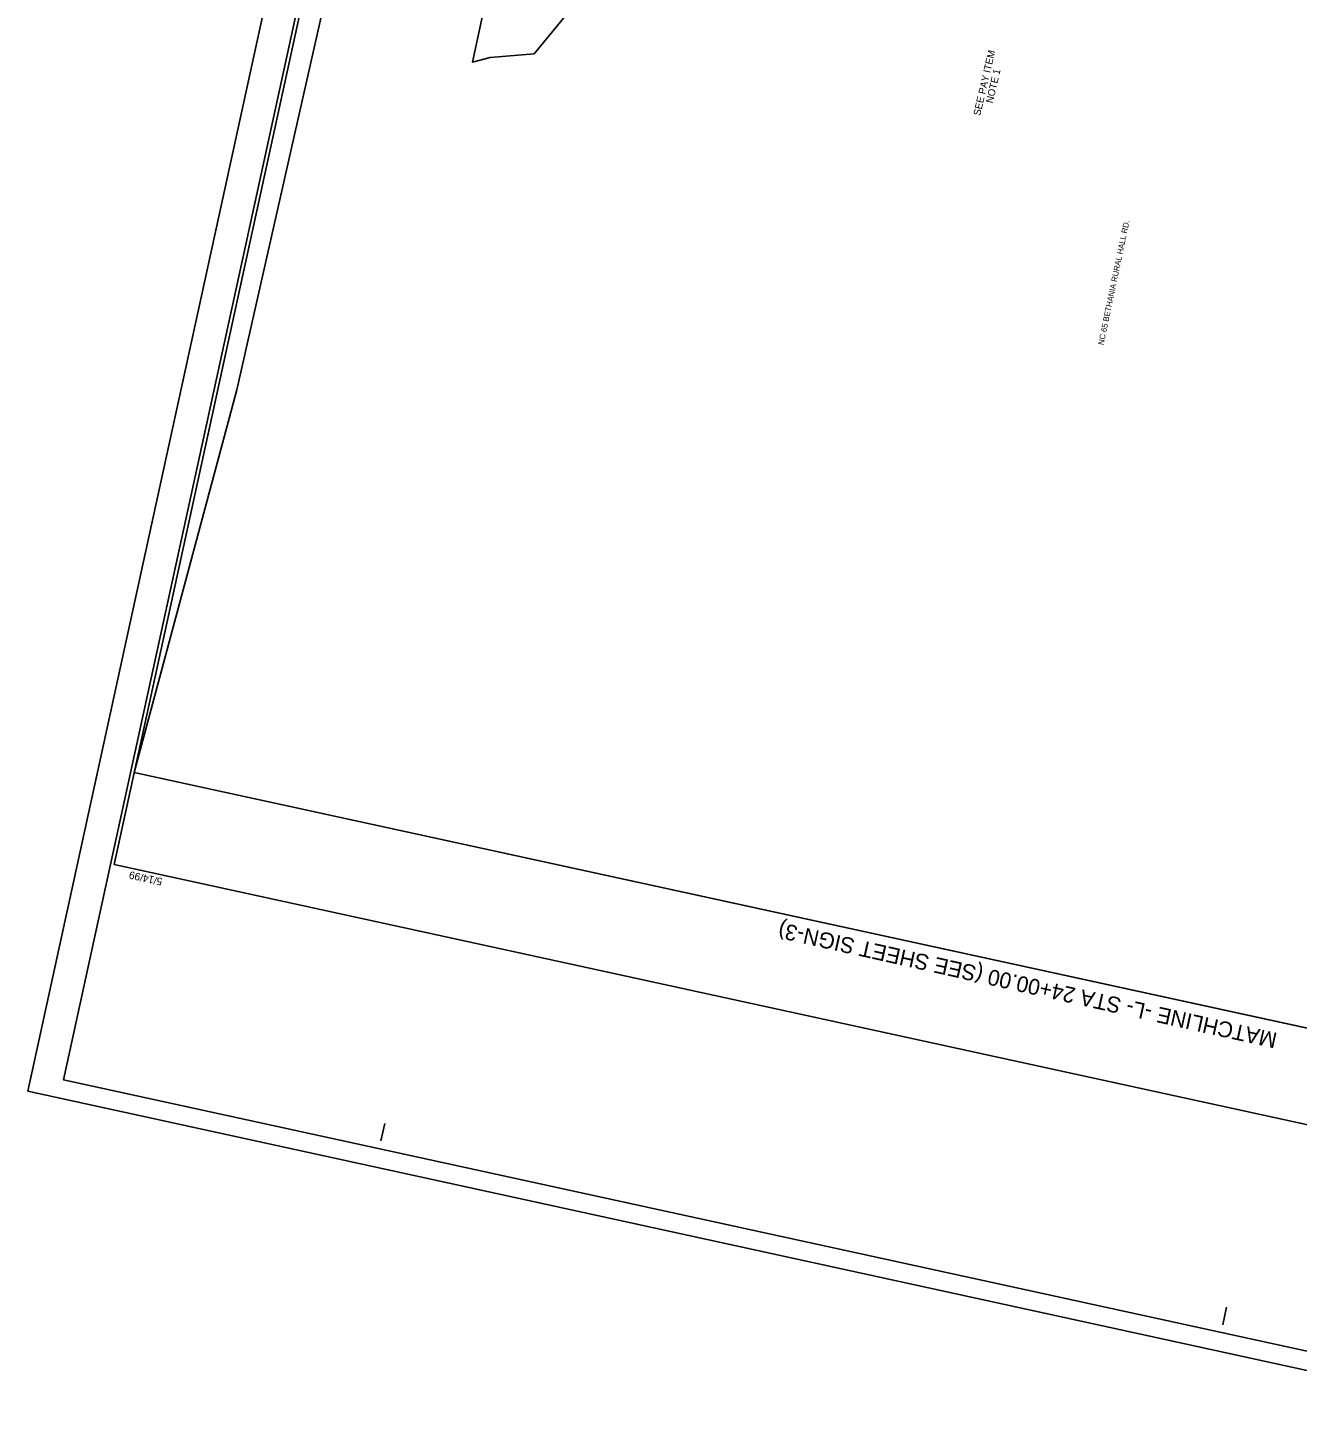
# Model space of a CAD drawing. Extents: x 1615829 to 1617263, y 900664 to 902544.
# Drawn here: x 1615829 to 1616713, y 900664 to 901639 of the extents above; entities that cross this region are included whole.
import ezdxf

# ---------------------------------------------------------------- set-up
doc = ezdxf.new("R2010")
doc.units = 0
for name, color, linetype in [('CTL Primary Horizontal and Vertical CELL', 7, 'Continuous'), ('CTL Primary Horizontal and Vertical Cogo Number', 7, 'Continuous'), ('CTL Secondary Horizontal and Vertical CELL', 7, 'Continuous'), ('Default', 7, 'Continuous'), ('Exist DTM Crownline Cogo Number', 7, 'Continuous'), ('Exist Roads Curbs Cogo Number', 7, 'Continuous'), ('Exist Roads Curbs Cogo Point CELL', 7, 'Continuous'), ('Exist Utilities Sanitary Sewer Manhole CELL', 7, 'Continuous')]:
    doc.layers.add(name, color=color, linetype=linetype)

msp = doc.modelspace()

# ---------------------------------------------------------------- linework, layer by layer
at = {"layer": 'CTL Primary Horizontal and Vertical CELL'}
msp.add_lwpolyline([(1616208.96, 902534.66), (1615853.55, 900906.5), (1616884.38, 900681.48), (1617239.79, 902309.64)], close=True, dxfattribs=at)
at = {"layer": 'CTL Primary Horizontal and Vertical Cogo Number'}
msp.add_lwpolyline([(1616187.99, 902543.84), (1615828.85, 900898.58), (1616903.54, 900663.99), (1617262.68, 902309.25)], close=True, dxfattribs=at)
at = {"layer": 'CTL Secondary Horizontal and Vertical CELL'}
for p, q in [((1615889.1, 901057.39), (1615889.1, 901057.39)), ((1616074.6, 900863.87), (1616077.27, 900876.09)), ((1616660.8, 900735.91), (1616663.46, 900748.13))]:
    msp.add_line(p, q, dxfattribs=at)
msp.add_lwpolyline([(1616208.79, 902521.9), (1615888.89, 901056.41), (1616914.73, 900832.48), (1617234.63, 902297.97)], close=True, dxfattribs=at)
at = {"layer": 'Exist DTM Crownline Cogo Number'}
msp.add_lwpolyline([(1616850.42, 902379.94), (1617227.49, 902296.2), (1617121.36, 901790.43), (1617088.18, 901641.75), (1617042.44, 901522.26), (1617032.35, 901430.63), (1617021.35, 901334.38), (1616928.77, 900896.77), (1615902.83, 901120.28), (1615974.27, 901386.7), (1616087.67, 901888.92), (1616145.49, 901879.24), (1616184.12, 901827.49), (1616138.37, 901614.97), (1616150.59, 901618.07), (1616181.32, 901620.66), (1616299.19, 901764.2), (1616120.07, 901933.32), (1616161.35, 902112.51), (1616179.69, 902310.42), (1616356.27, 902284.95), (1616372.44, 902359.01)], close=True, dxfattribs=at)
at = {"layer": 'Exist Roads Curbs Cogo Point CELL'}
msp.add_line((1615902.83, 901120.28), (1616928.77, 900896.77), dxfattribs=at)

# ---------------------------------------------------------------- texts
at = {"layer": 'CTL Secondary Horizontal and Vertical CELL'}
msp.add_text('5/14/99', height=5.25, rotation=167.68623, dxfattribs=at).set_placement((1615922.8, 901046.7))
at = {"layer": 'Default'}
for s, p in [('SEE PAY ITEM', (1616491.93, 901577.36)), ('NOTE 1', (1616500.67, 901585.98))]:
    msp.add_text(s, height=5, rotation=76.89482, dxfattribs=at).set_placement(p)
at = {"layer": 'Exist Roads Curbs Cogo Number'}
msp.add_text('MATCHLINE -L- STA 24+00.00 (SEE SHEET SIGN-3)', height=11, rotation=167.43355, dxfattribs=at).set_placement((1616699.38, 900938.92))
at = {"layer": 'Exist Utilities Sanitary Sewer Manhole CELL'}
msp.add_text('NC 65 BETHANIA RURAL HALL RD.', height=4, rotation=78.22466, dxfattribs=at).set_placement((1616577.86, 901417.7))

doc.saveas('drawing.dxf')
